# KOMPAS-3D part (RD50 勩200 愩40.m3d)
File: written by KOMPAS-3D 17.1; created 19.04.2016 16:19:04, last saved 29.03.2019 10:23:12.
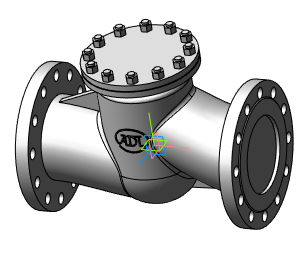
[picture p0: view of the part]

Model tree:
1. Операция без истории:2  (labels: Сталь 20  ГОСТ 1050-88)

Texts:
  RD50 Ду15 Ру40
  RD50 Ду20 Ру40
  RD50 Ду25 Ру40
  RD50 Ду32 Ру40
  RD50 Ду40 Ру40
  RD50 Ду50 Ру40
  RD50 Ду65 Ру40
  RD50 Ду80 Ру40
  RD50 Ду100 Ру40
  RD50 Ду125 Ру40
  RD50 Ду150 Ру40
  RD50 Ду200 Ру40
  RD50 Ду250 Ру40
  RD50 Ду300 Ру40
  RD50 Ду350 Ру40
  RD50 Ду400 Ру40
